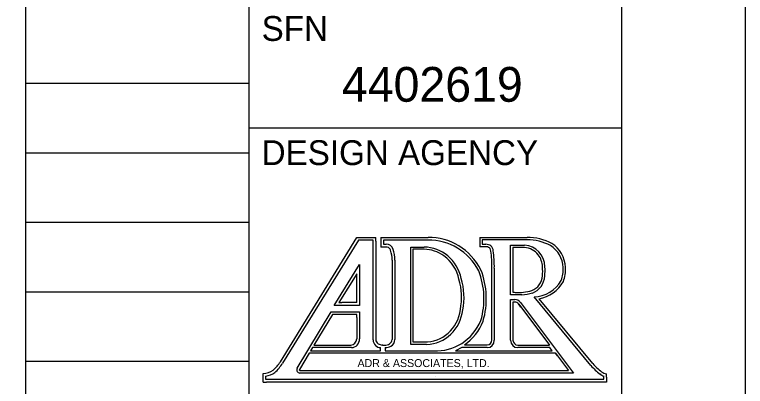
# Model space of a CAD drawing. Extents: x 0 to 34, y 0 to 22.
# Drawn here: x 31.054 to 34, y 3.959 to 5.456 of the extents above; entities that cross this region are included whole.
import ezdxf

# ---------------------------------------------------------------- set-up
doc = ezdxf.new("R2010")
doc.units = 0
for name, color, linetype in [('SC_Scratch2', 7, 'Continuous'), ('SH_Border', 7, 'Continuous'), ('SH_Cut_Line', 7, 'Continuous'), ('SH_Data', 7, 'Continuous')]:
    doc.layers.add(name, color=color, linetype=linetype)

msp = doc.modelspace()

# ---------------------------------------------------------------- linework, layer by layer
at = {"layer": 'SC_Scratch2'}
for p, q in [((31.1, 0.98), (31.1, 21.14)), ((32, 0.98), (32, 21.14)), ((31.1, 5.18), (32, 5.18)), ((31.1, 4.9), (32, 4.9)), ((31.1, 4.62), (32, 4.62)), ((31.1, 4.34), (32, 4.34)), ((31.1, 4.06), (32, 4.06))]:
    msp.add_line(p, q, dxfattribs=at)
at = {"layer": 'SH_Border'}
for p, q in [((32, 0.5), (32, 21.5)), ((32, 5), (33.5, 5))]:
    msp.add_line(p, q, dxfattribs=at)
msp.add_lwpolyline([(1.5, 21.5), (33.5, 21.5), (33.5, 0.5), (1.5, 0.5)], close=True, dxfattribs=at)
at = {"layer": 'SH_Cut_Line'}
msp.add_lwpolyline([(0, 0), (34, 0), (34, 22), (0, 22)], close=True, dxfattribs=at)
at = {"layer": 'SH_Data'}
for p, q in [((32.1254, 4.058), (32.4341, 4.5584)), ((32.4341, 4.5584), (32.5101, 4.5584)), ((32.5101, 4.5435), (32.5101, 4.5584)), ((32.5101, 4.5435), (32.5101, 4.1481)), ((32.53, 4.559), (32.53, 4.52)), ((32.53, 4.559), (32.721, 4.559)), ((32.929, 4.559), (32.929, 4.5215)), ((32.929, 4.559), (33.12, 4.559)), ((32.929, 4.559), (32.929, 4.5215)), ((32.929, 4.559), (33.12, 4.559)), ((32.5442, 4.52), (32.53, 4.52)), ((32.552, 4.52), (32.5442, 4.52)), ((32.7049, 4.511), (32.6598, 4.511)), ((32.6598, 4.511), (32.6598, 4.1379)), ((32.9432, 4.5215), (32.929, 4.5215)), ((32.9432, 4.5215), (32.929, 4.5215)), ((32.951, 4.5215), (32.9432, 4.5215)), ((32.5757, 4.4673), (32.5757, 4.1481)), ((32.9785, 4.1462), (32.9785, 4.4347)), ((32.4331, 4.4128), (32.3615, 4.2966)), ((32.4331, 4.3944), (32.4331, 4.4128)), ((32.4331, 4.2966), (32.4331, 4.3944)), ((33.3849, 4.0506), (33.1692, 4.3119)), ((32.3615, 4.2966), (32.3728, 4.2966)), ((32.4331, 4.2966), (32.3728, 4.2966)), ((33.0868, 4.2896), (33.2106, 4.1252)), ((32.3351, 4.2491), (32.2609, 4.1252)), ((32.4331, 4.2491), (32.3351, 4.2491)), ((32.4331, 4.2366), (32.4331, 4.2491)), ((32.4331, 4.2366), (32.4331, 4.1502)), ((32.2609, 4.1252), (32.2722, 4.1252)), ((32.2722, 4.1252), (32.4094, 4.1252)), ((32.5384, 4.1252), (32.5356, 4.1254)), ((32.5384, 4.1252), (32.5356, 4.1254)), ((32.5384, 4.1252), (32.5453, 4.1252)), ((32.6598, 4.1379), (32.6683, 4.1379)), ((32.6683, 4.1379), (32.7049, 4.1379)), ((32.8673, 4.1262), (32.9595, 4.1262)), ((33.0822, 4.1252), (33.2106, 4.1252)), ((33.2351, 4.0922), (33.2867, 4.0234)), ((32.0556, 3.9766), (32.0556, 4.0109)), ((32.2043, 4.0234), (32.2112, 4.0234)), ((32.2112, 4.0234), (33.2867, 4.0234)), ((33.4404, 3.996), (33.4404, 4.0102)), ((32.75, 4), (32.75, 4)), ((33.4404, 3.996), (33.4404, 3.9766)), ((32.0556, 3.9766), (32.0701, 3.9766)), ((33.4404, 3.9766), (32.0701, 3.9766))]:
    msp.add_line(p, q, dxfattribs=at)
for points in [[(32.4996, 4.1463), (32.4996, 4.5474), (32.4398, 4.5474), (32.1341, 4.052)], [(32.721, 4.5474), (32.541, 4.5474), (32.541, 4.5313), (32.552, 4.5313)], [(33.12, 4.549), (32.9385, 4.549), (32.9385, 4.5315), (32.9536, 4.5315)], [(32.6514, 4.1276), (32.6514, 4.52), (32.7049, 4.52)], [(33.0537, 4.5278), (33.1102, 4.5278)], [(33.0987, 4.3276), (33.0537, 4.3276), (33.0537, 4.5278)], [(33.11, 4.5178), (33.0632, 4.5178), (33.0632, 4.3384)], [(32.445, 4.2841), (32.3424, 4.2841), (32.445, 4.4504), (32.445, 4.2841)], [(32.5864, 4.4673), (32.5864, 4.4668), (32.5864, 4.1481)], [(32.988, 4.4346), (32.988, 4.1452)], [(33.0537, 4.1452), (33.0537, 4.3086), (33.0709, 4.3086)], [(33.3772, 4.0431), (33.1487, 4.32)], [(33.0932, 4.2972), (33.3075, 4.0126), (32.2038, 4.0126)], [(33.0709, 4.2986), (33.0632, 4.2986), (33.0632, 4.1452)], [(33.0954, 4.2782), (33.0857, 4.291)], [(32.1938, 4.0318), (32.3298, 4.2591), (32.445, 4.2591), (32.445, 4.1502)], [(32.715, 4.1276), (32.6514, 4.1276)], [(32.8673, 4.1262), (32.8894, 4.1262)], [(33.0822, 4.1252), (33.086, 4.1252)], [(32.4118, 4.1152), (32.2551, 4.1152), (32.2476, 4.1027), (32.5292, 4.1027), (32.5292, 4.1152)], [(32.5484, 4.1152), (32.5484, 4.1027), (32.7432, 4.1027)], [(32.9595, 4.1152), (32.857, 4.1152), (32.8311, 4.1027), (33.2217, 4.1027), (33.2123, 4.1152), (33.0822, 4.1152)], [(33.2426, 4.0822), (33.2351, 4.0922), (32.2412, 4.0922), (32.2022, 4.0272)], [(32.066, 4.0006), (32.066, 3.9876), (33.4299, 3.9876), (33.4299, 4.0006)]]:
    msp.add_lwpolyline(points, dxfattribs=at)
for centre, major_axis, start_param, end_param in [((32.7243, 4.3082), (0, 0.2509), 5.209873, 6.297313), ((32.726, 4.3081), (0, 0.2394), 5.218006, 6.305445), ((33.1223, 4.3329), (0, 0.2261), 5.810103, 6.294452), ((33.1223, 4.3329), (0, 0.2261), 5.810103, 6.294452), ((33.1224, 4.3335), (0, 0.2155), 5.814829, 6.29527), ((32.552, 4.5), (0, 0.0313), 5.060756, 6.283185), ((32.552, 4.5), (0, 0.02), 5.294753, 6.283185), ((32.552, 4.5), (0, 0.02), 5.060756, 5.294753), ((32.4775, 4.4716), (0, 0.1147), 4.675194, 5.060756), ((32.7039, 4.3572), (0, 0.1628), 4.938334, 6.276888), ((32.7028, 4.3574), (0, 0.1537), 5.684676, 6.268828), ((32.9522, 4.4897), (0, 0.0318), 5.717883, 6.322951), ((32.9522, 4.4897), (0, 0.0418), 5.696071, 6.248499), ((32.9551, 4.5016), (0, 0.0204), 5.34604, 5.529903), ((32.9551, 4.5016), (0, 0.0204), 4.827568, 5.34604), ((32.9551, 4.5016), (0, 0.0204), 4.827568, 5.34604), ((32.9551, 4.5016), (0, 0.0304), 4.832872, 5.561833), ((33.1063, 4.4378), (0, 0.08), 5.402738, 6.234422), ((33.1063, 4.4378), (0, 0.09), 4.740194, 6.23721), ((33.1638, 4.4336), (0, 0.1067), 4.750292, 5.755325), ((33.1638, 4.4336), (0, 0.1167), 4.753214, 5.755325), ((33.1638, 4.4336), (0, 0.1167), 4.753214, 5.755325), ((32.4775, 4.4716), (0, 0.1034), 4.671123, 5.060756), ((32.7028, 4.3574), (0, 0.1537), 4.930275, 5.684676), ((32.5748, 4.4427), (0, 0.425), 4.693619, 4.857063), ((32.5748, 4.4427), (0, 0.425), 4.693619, 4.857063), ((32.5748, 4.4427), (0, 0.435), 4.693836, 4.856756), ((33.1063, 4.4378), (0, 0.08), 4.740194, 5.402738), ((33.1063, 4.4378), (0, 0.08), 4.740194, 5.402738), ((32.6675, 4.3117), (0, 0.2934), 4.410917, 5.105556), ((32.6675, 4.3117), (0, 0.3034), 4.410917, 5.105556), ((33.0035, 4.4239), (0, 0.1889), 4.608112, 4.797709), ((33.0035, 4.4239), (0, 0.1889), 4.608112, 4.797709), ((33.0086, 4.4238), (0, 0.1936), 4.607961, 4.797558), ((33.166, 4.4266), (0, 0.1049), 4.309756, 4.818512), ((33.166, 4.4266), (0, 0.1149), 4.303317, 4.815541), ((33.166, 4.4266), (0, 0.1149), 4.303317, 4.815541), ((32.6246, 4.3176), (0, 0.2435), 4.507644, 5.016706), ((32.626, 4.3177), (0, 0.2524), 4.509144, 5.018206), ((33.1182, 4.4083), (0, -0.0672), 0.330696, 1.511334), ((33.1182, 4.4083), (0, -0.0672), 0.330696, 1.511334), ((33.1178, 4.4086), (0, -0.0777), 0.32607, 1.506707), ((33.1467, 4.457), (0, -0.1371), 0.015856, 1.021186), ((33.1467, 4.457), (0, -0.1471), 0.16231, 1.026165), ((33.1467, 4.457), (0, -0.1471), 0.16231, 1.026165), ((33.0851, 4.556), (0, -0.2188), 6.177822, 6.219099), ((33.0851, 4.556), (0, -0.2188), 6.219099, 6.545404), ((33.0851, 4.556), (0, -0.2188), 6.219099, 6.545404), ((33.0851, 4.556), (0, -0.2288), 0.06267, 0.262218), ((33.0709, 4.2786), (0, 0.03), 5.382662, 6.283185), ((33.0709, 4.2786), (0, 0.02), 5.382662, 6.283185), ((32.7099, 4.2877), (0, -0.1499), 6.247489, 7.723), ((32.7099, 4.2877), (0, -0.1602), 0.033392, 1.439815), ((32.7557, 4.307), (0, -0.2047), 6.218561, 7.439351), ((32.7556, 4.3048), (0, -0.2139), 0.582172, 1.170799), ((32.4094, 4.1502), (0, -0.025), 0, 1.570796), ((32.4118, 4.1502), (0, -0.035), 0, 1.570796), ((32.5292, 4.1463), (0, -0.0311), 4.712389, 6.28383), ((32.5291, 4.1481), (0, -0.02), 4.712389, 5.785309), ((32.5401, 4.1695), (0, -0.0444), 5.785308, 6.174936), ((32.5456, 4.1695), (0, -0.0444), 6.276852, 6.781063), ((32.5567, 4.1481), (0, -0.02), 0.497877, 1.570796), ((32.5567, 4.1481), (0, -0.0313), 0.497877, 1.570796), ((32.9595, 4.1462), (0, -0.02), 0, 1.570796), ((32.9595, 4.1452), (0, -0.03), 0, 1.570796), ((33.0822, 4.1452), (0, -0.03), 4.712389, 6.283185), ((33.0822, 4.1452), (0, -0.02), 4.712389, 6.283185), ((32.5506, 4.1599), (0, -0.0447), 6.230381, 6.780961), ((31.9988, 4.1451), (0, -0.1592), 0.707735, 0.991966), ((31.9988, 4.1451), (0, -0.1702), 0.704048, 0.991966), ((33.5477, 4.2078), (0, -0.2436), 5.454898, 5.668061), ((33.5477, 4.2078), (0, -0.2326), 5.454898, 5.66951), ((33.5477, 4.2078), (0, -0.2326), 5.454898, 5.66951), ((32.0559, 4.0887), (0, -0.0777), 6.278764, 6.875053), ((32.0559, 4.0887), (0, -0.0887), 0.120377, 0.599173), ((32.2038, 4.0251), (0, -0.0125), 4.150117, 6.283185), ((32.2043, 4.0259), (0, -0.0025), 4.150111, 6.283185), ((33.4405, 4.0437), (0, -0.0445), 5.61027, 6.031177), ((33.4405, 4.0437), (0, -0.0335), 5.601331, 6.280654), ((33.4405, 4.0437), (0, -0.0335), 5.601331, 6.280654)]:
    msp.add_ellipse(centre, major_axis=major_axis, ratio=0.95, start_param=start_param, end_param=end_param, dxfattribs=at)

# ---------------------------------------------------------------- texts
for s, height, p in [('SFN', 0.1, (32.05, 5.35)), ('4402619', 0.14, (32.3737, 5.105)), ('DESIGN AGENCY', 0.1, (32.05, 4.85))]:
    msp.add_text(s, height=height, dxfattribs=at).set_placement(p)
msp.add_text('ADR & ASSOCIATES, LTD.', height=0.032, rotation=360, dxfattribs=at).set_placement((32.4365, 4.0368))

doc.saveas('drawing.dxf')
